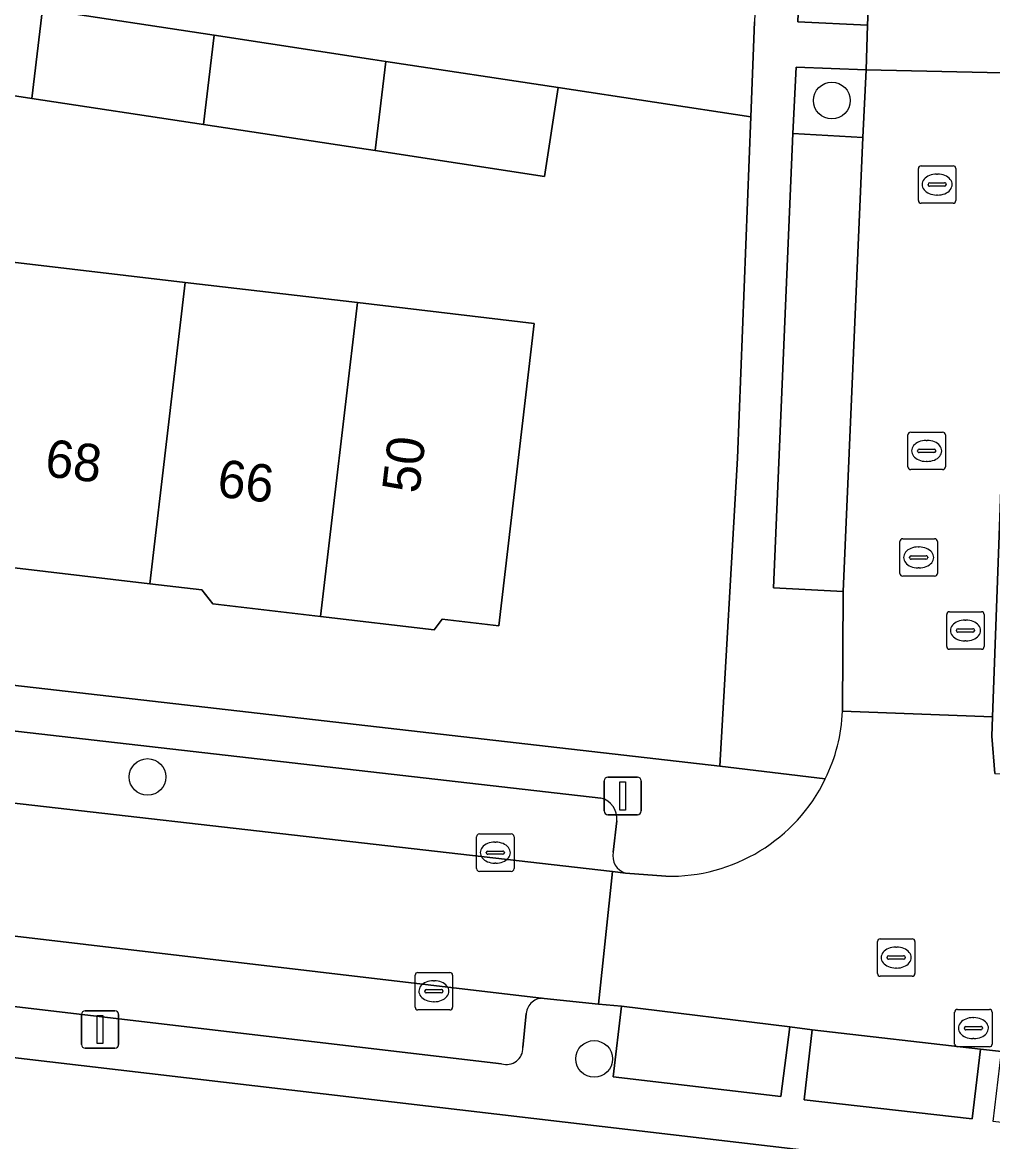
# Model space of a CAD drawing. Extents: x 162250 to 162661, y 380743 to 381606.
# Drawn here: x 162316.6 to 162342.5, y 380958.27 to 380988.14 of the extents above; entities that cross this region are included whole.
import ezdxf

# ---------------------------------------------------------------- set-up
doc = ezdxf.new("R2010")
doc.units = 0
for name, color, linetype in [('IMGEO_Boom', 7, 'Continuous'), ('IMGEO_Erf', 7, 'Continuous'), ('IMGEO_Groenvoorziening', 7, 'Continuous'), ('IMGEO_Kolk', 7, 'Continuous'), ('IMGEO_Lichtmast', 7, 'Continuous'), ('IMGEO_Pand', 7, 'Continuous'), ('IMGEO_Pand_nummerreeks', 7, 'Continuous'), ('IMGEO_Parkeervlak_open', 7, 'Continuous'), ('IMGEO_Rijbaan_lokaal_open', 7, 'Continuous'), ('IMGEO_Rioolput', 7, 'Continuous'), ('IMGEO_Voetpad_open', 7, 'Continuous')]:
    doc.layers.add(name, color=color, linetype=linetype)

msp = doc.modelspace()

# ---------------------------------------------------------------- linework, layer by layer
at = {"layer": 'IMGEO_Boom'}
for centre in [(162338.206, 380986.051), (162319.942, 380968.001), (162331.862, 380960.479)]:
    msp.add_circle(centre, 0.489, dxfattribs=at)
at = {"layer": 'IMGEO_Erf'}
msp.add_lwpolyline([(162321.44, 380985.411), (162316.858, 380986.109), (162312.278, 380986.806), (162307.698, 380987.503), (162303.115, 380988.2), (162298.535, 380988.897), (162294.161, 380989.563), (162293.955, 380989.594), (162289.217, 380990.315), (162289.578, 380992.684), (162285.702, 380993.275), (162283.759, 380976.44), (162283.492, 380974.216), (162335.219, 380968.294), (162335.689, 380976.508), (162336.042, 380985.614), (162330.898, 380986.396), (162330.538, 380984.027), (162326.021, 380984.714), (162325.595, 380984.779)], close=True, dxfattribs=at)
for points in [[(162297.948, 380983.904), (162302.547, 380983.363), (162307.147, 380982.822), (162311.746, 380982.282), (162316.345, 380981.741), (162320.945, 380981.2), (162325.544, 380980.66), (162330.262, 380980.105), (162329.314, 380972.033), (162327.806, 380972.21), (162327.594, 380971.925), (162324.559, 380972.282), (162321.687, 380972.62), (162321.391, 380972.995), (162319.999, 380973.159), (162315.4, 380973.699), (162310.801, 380974.24), (162306.201, 380974.781), (162301.602, 380975.321), (162297.003, 380975.862)], [(162396.364, 380951.153), (162282.368, 380964.496)]]:
    msp.add_lwpolyline(points, dxfattribs=at)
at = {"layer": 'IMGEO_Groenvoorziening'}
msp.add_lwpolyline([(162339.119, 380986.868), (162337.251, 380986.943), (162337.162, 380985.171), (162339.037, 380985.062)], close=True, dxfattribs=at)
at = {"layer": 'IMGEO_Kolk'}
for p, q in [((162340.515, 380983.383), (162340.515, 380984.235)), ((162340.59, 380984.309), (162341.442, 380984.309)), ((162341.516, 380984.235), (162341.516, 380983.383)), ((162341.003, 380984.089), (162341.028, 380984.089)), ((162340.774, 380983.803), (162340.774, 380983.815)), ((162341.212, 380983.766), (162340.814, 380983.766)), ((162340.817, 380983.852), (162341.215, 380983.852)), ((162341.258, 380983.815), (162341.258, 380983.803)), ((162341.026, 380983.529), (162341.001, 380983.529)), ((162341.442, 380983.309), (162340.59, 380983.309)), ((162340.236, 380976.276), (162340.236, 380977.128)), ((162340.311, 380977.202), (162341.163, 380977.202)), ((162341.237, 380977.128), (162341.237, 380976.276)), ((162340.724, 380976.982), (162340.749, 380976.982)), ((162340.495, 380976.696), (162340.495, 380976.708)), ((162340.933, 380976.659), (162340.535, 380976.659)), ((162340.538, 380976.745), (162340.936, 380976.745)), ((162340.979, 380976.708), (162340.979, 380976.696)), ((162341.163, 380976.202), (162340.311, 380976.202)), ((162340.747, 380976.422), (162340.722, 380976.422)), ((162328.723, 380965.556), (162328.723, 380966.408)), ((162328.798, 380966.482), (162329.65, 380966.482)), ((162329.724, 380966.408), (162329.724, 380965.556)), ((162329.025, 380966.025), (162329.423, 380966.025)), ((162329.211, 380966.262), (162329.236, 380966.262)), ((162328.982, 380965.976), (162328.982, 380965.988)), ((162329.42, 380965.939), (162329.022, 380965.939)), ((162329.466, 380965.988), (162329.466, 380965.976)), ((162329.65, 380965.482), (162328.798, 380965.482)), ((162329.234, 380965.702), (162329.209, 380965.702)), ((162327.159, 380962.785), (162328.011, 380962.785)), ((162327.084, 380961.859), (162327.084, 380962.711)), ((162327.572, 380962.565), (162327.597, 380962.565)), ((162328.085, 380962.711), (162328.085, 380961.859)), ((162327.343, 380962.279), (162327.343, 380962.291)), ((162327.781, 380962.242), (162327.383, 380962.242)), ((162327.386, 380962.328), (162327.784, 380962.328)), ((162327.827, 380962.291), (162327.827, 380962.279)), ((162327.595, 380962.005), (162327.57, 380962.005)), ((162328.011, 380961.785), (162327.159, 380961.785))]:
    msp.add_line(p, q, dxfattribs=at)
for points in [[(162340.515, 380983.383), (162340.515, 380984.235)], [(162340.59, 380984.309), (162341.442, 380984.309)], [(162341.516, 380984.235), (162341.516, 380983.383)], [(162341.442, 380983.309), (162340.59, 380983.309)], [(162340.236, 380976.276), (162340.236, 380977.128)], [(162340.311, 380977.202), (162341.163, 380977.202)], [(162341.237, 380977.128), (162341.237, 380976.276)], [(162341.163, 380976.202), (162340.311, 380976.202)], [(162328.723, 380965.556), (162328.723, 380966.408)], [(162328.798, 380966.482), (162329.65, 380966.482)], [(162329.724, 380966.408), (162329.724, 380965.556)], [(162329.65, 380965.482), (162328.798, 380965.482)], [(162327.159, 380962.785), (162328.011, 380962.785)], [(162327.084, 380961.859), (162327.084, 380962.711)], [(162328.085, 380962.711), (162328.085, 380961.859)], [(162328.011, 380961.785), (162327.159, 380961.785)]]:
    msp.add_lwpolyline(points, dxfattribs=at)
for centre, radius, start, end in [((162340.592, 380984.233), 0.0765, 91.552, 178.448), ((162340.592, 380984.233), 0.0765, 91.552, 178.448), ((162341.44, 380984.233), 0.0765, 1.552, 88.448), ((162341.44, 380984.233), 0.0765, 1.552, 88.448), ((162340.814, 380983.812), 0.0403, 85.8775, 175.7526), ((162340.811, 380983.802), 0.0366, 178.938, 274.7102), ((162341.215, 380983.809), 0.043, 264.8664, 352.4533), ((162341.219, 380983.814), 0.0386, 1.7309, 96.639), ((162340.592, 380983.385), 0.0765, 181.552, 268.448), ((162340.592, 380983.385), 0.0765, 181.552, 268.448), ((162341.44, 380983.385), 0.0765, 271.552, 358.448), ((162341.44, 380983.385), 0.0765, 271.552, 358.448), ((162340.313, 380977.126), 0.0765, 91.552, 178.448), ((162340.313, 380977.126), 0.0765, 91.552, 178.448), ((162341.161, 380977.126), 0.0765, 1.552, 88.448), ((162341.161, 380977.126), 0.0765, 1.552, 88.448), ((162340.535, 380976.705), 0.0403, 85.8775, 175.7526), ((162340.532, 380976.695), 0.0366, 178.938, 274.7102), ((162340.936, 380976.702), 0.043, 264.8664, 352.4533), ((162340.94, 380976.707), 0.0386, 1.7309, 96.639), ((162340.313, 380976.278), 0.0765, 181.552, 268.448), ((162340.313, 380976.278), 0.0765, 181.552, 268.448), ((162341.161, 380976.278), 0.0765, 271.552, 358.448), ((162341.161, 380976.278), 0.0765, 271.552, 358.448), ((162328.8, 380966.406), 0.0765, 91.552, 178.448), ((162328.8, 380966.406), 0.0765, 91.552, 178.448), ((162329.648, 380966.406), 0.0765, 1.552, 88.448), ((162329.648, 380966.406), 0.0765, 1.552, 88.448), ((162329.022, 380965.985), 0.0403, 85.8775, 175.7526), ((162329.427, 380965.987), 0.0386, 1.7309, 96.639), ((162329.019, 380965.975), 0.0366, 178.938, 274.7102), ((162329.423, 380965.982), 0.043, 264.8664, 352.4533), ((162328.8, 380965.558), 0.0765, 181.552, 268.448), ((162328.8, 380965.558), 0.0765, 181.552, 268.448), ((162329.648, 380965.558), 0.0765, 271.552, 358.448), ((162329.648, 380965.558), 0.0765, 271.552, 358.448), ((162327.161, 380962.709), 0.0765, 91.552, 178.448), ((162327.161, 380962.709), 0.0765, 91.552, 178.448), ((162328.009, 380962.709), 0.0765, 1.552, 88.448), ((162328.009, 380962.709), 0.0765, 1.552, 88.448), ((162327.383, 380962.288), 0.0403, 85.8775, 175.7526), ((162327.38, 380962.278), 0.0366, 178.938, 274.7102), ((162327.784, 380962.285), 0.043, 264.8664, 352.4533), ((162327.788, 380962.29), 0.0386, 1.7309, 96.639), ((162327.161, 380961.861), 0.0765, 181.552, 268.448), ((162327.161, 380961.861), 0.0765, 181.552, 268.448), ((162328.009, 380961.861), 0.0765, 271.552, 358.448), ((162328.009, 380961.861), 0.0765, 271.552, 358.448)]:
    msp.add_arc(centre, radius, start, end, dxfattribs=at)
for centre, major_axis, ratio, start_param, end_param in [((162341.002, 380983.809), (-0.387, 0.002), 0.722429, 4.712389, 7.853982), ((162341.027, 380983.809), (-0.39, 0.002), 0.717154, 1.570796, 4.712389), ((162340.723, 380976.702), (-0.387, 0.002), 0.722429, 4.712389, 7.853982), ((162340.748, 380976.702), (-0.39, 0.002), 0.717154, 1.570796, 4.712389), ((162329.21, 380965.982), (-0.387, 0.002), 0.722429, 4.712389, 7.853982), ((162329.235, 380965.982), (-0.39, 0.002), 0.717154, 1.570796, 4.712389), ((162327.571, 380962.285), (-0.387, 0.002), 0.722429, 4.712389, 7.853982), ((162327.596, 380962.285), (-0.39, 0.002), 0.717154, 1.570796, 4.712389)]:
    msp.add_ellipse(centre, major_axis=major_axis, ratio=ratio, start_param=start_param, end_param=end_param, dxfattribs=at)
at = {"layer": 'IMGEO_Lichtmast'}
for p, q in [((162332.128, 380967.095), (162332.128, 380967.895)), ((162332.128, 380967.895), (162332.128, 380967.095)), ((162332.228, 380967.995), (162333.018, 380967.995)), ((162333.018, 380967.995), (162332.228, 380967.995)), ((162333.118, 380967.895), (162333.118, 380967.095)), ((162333.118, 380967.095), (162333.118, 380967.895)), ((162333.018, 380966.995), (162332.228, 380966.995)), ((162332.228, 380966.995), (162333.018, 380966.995)), ((162318.181, 380960.864), (162318.181, 380961.664)), ((162318.181, 380961.664), (162318.181, 380960.864)), ((162318.281, 380961.764), (162319.071, 380961.764)), ((162319.071, 380961.764), (162318.281, 380961.764)), ((162319.171, 380961.664), (162319.171, 380960.864)), ((162319.171, 380960.864), (162319.171, 380961.664)), ((162319.071, 380960.764), (162318.281, 380960.764)), ((162318.281, 380960.764), (162319.071, 380960.764))]:
    msp.add_line(p, q, dxfattribs=at)
for points in [[(162332.548, 380967.87), (162332.698, 380967.87), (162332.698, 380967.12), (162332.548, 380967.12), (162332.548, 380967.87)], [(162318.601, 380961.639), (162318.751, 380961.639), (162318.751, 380960.889), (162318.601, 380960.889), (162318.601, 380961.639)]]:
    msp.add_lwpolyline(points, dxfattribs=at)
for centre, start, end in [((162332.228, 380967.895), 90, 180), ((162332.228, 380967.895), 90, 180), ((162333.018, 380967.895), 0, 90), ((162333.018, 380967.895), 360, 90), ((162332.228, 380967.095), 180, 270), ((162332.228, 380967.095), 180, 270), ((162333.018, 380967.095), 270, 0), ((162333.018, 380967.095), 270, 0), ((162318.281, 380961.664), 90, 180), ((162318.281, 380961.664), 90, 180), ((162319.071, 380961.664), 0, 90), ((162319.071, 380961.664), 360, 90), ((162318.281, 380960.864), 180, 270), ((162318.281, 380960.864), 180, 270), ((162319.071, 380960.864), 270, 0), ((162319.071, 380960.864), 270, 0)]:
    msp.add_arc(centre, 0.1, start, end, dxfattribs=at)
at = {"layer": 'IMGEO_Pand'}
for points in [[(162312.278, 380986.806), (162316.858, 380986.109), (162317.138, 380988.49), (162312.557, 380989.187)], [(162321.721, 380987.792), (162317.138, 380988.49), (162316.858, 380986.109), (162321.44, 380985.411)], [(162321.721, 380987.792), (162321.44, 380985.411), (162325.595, 380984.779), (162326.021, 380984.714), (162326.301, 380987.095), (162325.955, 380987.148)], [(162326.021, 380984.714), (162330.538, 380984.027), (162330.898, 380986.396), (162326.301, 380987.095)], [(162316.345, 380981.741), (162315.4, 380973.699), (162319.999, 380973.159), (162320.945, 380981.2)], [(162325.544, 380980.66), (162320.945, 380981.2), (162319.999, 380973.159), (162321.391, 380972.995), (162321.687, 380972.62), (162324.559, 380972.282)], [(162325.544, 380980.66), (162324.559, 380972.282), (162327.594, 380971.925), (162327.806, 380972.21), (162329.314, 380972.033), (162330.262, 380980.105)]]:
    msp.add_lwpolyline(points, close=True, dxfattribs=at)
at = {"layer": 'IMGEO_Parkeervlak_open'}
for points in [[(162340.038, 381010.111), (162338.156, 381010.198), (162337.294, 380988.148), (162339.157, 380988.064), (162339.37, 380992.927)], [(162344.989, 380985.516), (162343.084, 380985.588), (162342.495, 380969.61), (162342.476, 380969.092), (162342.553, 380968.091), (162344.349, 380968.083)], [(162339.037, 380985.062), (162337.162, 380985.171), (162336.646, 380973.052), (162338.509, 380972.948)], [(162337.083, 380961.332), (162332.589, 380961.89), (162332.373, 380959.999), (162336.845, 380959.473)], [(162337.683, 380961.253), (162337.463, 380959.389), (162341.953, 380958.882), (162342.172, 380960.742)]]:
    msp.add_lwpolyline(points, close=True, dxfattribs=at)
for points in [[(162332.037, 380967.44), (162286.174, 380972.683)], [(162284.995, 380970.888), (162332.355, 380965.483), (162332.699, 380965.436)], [(162330.529, 380962.093), (162284.836, 380967.471)], [(162332.37, 380965.994), (162332.469, 380966.833)], [(162285.595, 380965.499), (162329.39, 380960.351)], [(162329.959, 380960.782), (162330.052, 380961.693)]]:
    msp.add_lwpolyline(points, dxfattribs=at)
for centre, radius, start, end in [((162331.902, 380966.887), 0.569, 354.5842, 76.2945), ((162332.839, 380965.894), 0.479, 168.0185, 253.0292), ((162330.482, 380961.665), 0.431, 83.6791, 176.2856), ((162329.526, 380960.762), 0.433, 251.6612, 2.6244)]:
    msp.add_arc(centre, radius, start, end, dxfattribs=at)
at = {"layer": 'IMGEO_Rijbaan_lokaal_open'}
for points in [[(162339.157, 380988.064), (162339.119, 380986.868), (162343.163, 380986.78), (162343.397, 380992.747), (162339.37, 380992.927)], [(162343.084, 380985.588), (162343.163, 380986.78), (162339.119, 380986.868), (162339.037, 380985.062), (162338.509, 380972.948), (162338.492, 380969.758), (162342.495, 380969.61)], [(162284.995, 380970.888), (162284.107, 380971.014), (162283.032, 380971.129), (162282.665, 380967.703), (162283.759, 380967.586), (162284.836, 380967.471), (162330.529, 380962.093), (162331.977, 380961.942), (162332.355, 380965.483)]]:
    msp.add_lwpolyline(points, close=True, dxfattribs=at)
for points in [[(162342.553, 380968.091), (162342.476, 380969.092), (162342.495, 380969.61), (162338.492, 380969.758)], [(162333.779, 380965.354), (162332.699, 380965.436), (162332.355, 380965.483), (162331.977, 380961.942), (162332.589, 380961.89), (162337.083, 380961.332), (162337.683, 380961.253), (162342.172, 380960.742), (162342.735, 380960.674), (162346.981, 380960.157), (162347.688, 380960.071), (162348.113, 380963.62), (162347.022, 380963.772)]]:
    msp.add_lwpolyline(points, dxfattribs=at)
for centre, radius, start, end in [((162333.909, 380969.959), 4.587, 333.9951, 357.486), ((162333.887, 380969.961), 4.608, 268.663, 334.0969)]:
    msp.add_arc(centre, radius, start, end, dxfattribs=at)
at = {"layer": 'IMGEO_Rioolput'}
for p, q in [((162340.022, 380973.433), (162340.022, 380974.285)), ((162340.097, 380974.359), (162340.949, 380974.359)), ((162340.51, 380974.139), (162340.535, 380974.139)), ((162341.023, 380974.285), (162341.023, 380973.433)), ((162340.281, 380973.853), (162340.281, 380973.865)), ((162340.719, 380973.816), (162340.321, 380973.816)), ((162340.324, 380973.902), (162340.722, 380973.902)), ((162340.765, 380973.865), (162340.765, 380973.853)), ((162340.533, 380973.579), (162340.508, 380973.579)), ((162340.949, 380973.359), (162340.097, 380973.359)), ((162341.272, 380971.484), (162341.272, 380972.336)), ((162341.347, 380972.41), (162342.199, 380972.41)), ((162342.273, 380972.336), (162342.273, 380971.484)), ((162341.76, 380972.19), (162341.785, 380972.19)), ((162341.531, 380971.904), (162341.531, 380971.916)), ((162341.969, 380971.867), (162341.571, 380971.867)), ((162341.574, 380971.953), (162341.972, 380971.953)), ((162342.015, 380971.916), (162342.015, 380971.904)), ((162342.199, 380971.41), (162341.347, 380971.41)), ((162341.783, 380971.63), (162341.758, 380971.63)), ((162339.498, 380963.683), (162340.35, 380963.683)), ((162339.423, 380962.757), (162339.423, 380963.609)), ((162339.911, 380963.463), (162339.936, 380963.463)), ((162340.424, 380963.609), (162340.424, 380962.757)), ((162339.682, 380963.177), (162339.682, 380963.189)), ((162340.12, 380963.14), (162339.722, 380963.14)), ((162339.725, 380963.226), (162340.123, 380963.226)), ((162340.166, 380963.189), (162340.166, 380963.177)), ((162339.934, 380962.903), (162339.909, 380962.903)), ((162340.35, 380962.683), (162339.498, 380962.683)), ((162341.484, 380960.874), (162341.484, 380961.726)), ((162341.559, 380961.8), (162342.411, 380961.8)), ((162341.972, 380961.58), (162341.997, 380961.58)), ((162342.485, 380961.726), (162342.485, 380960.874)), ((162341.743, 380961.294), (162341.743, 380961.306)), ((162342.181, 380961.257), (162341.783, 380961.257)), ((162341.786, 380961.343), (162342.184, 380961.343)), ((162342.227, 380961.306), (162342.227, 380961.294)), ((162341.995, 380961.02), (162341.97, 380961.02)), ((162342.411, 380960.8), (162341.559, 380960.8))]:
    msp.add_line(p, q, dxfattribs=at)
for points in [[(162340.022, 380973.433), (162340.022, 380974.285)], [(162340.097, 380974.359), (162340.949, 380974.359)], [(162341.023, 380974.285), (162341.023, 380973.433)], [(162340.949, 380973.359), (162340.097, 380973.359)], [(162341.272, 380971.484), (162341.272, 380972.336)], [(162341.347, 380972.41), (162342.199, 380972.41)], [(162342.273, 380972.336), (162342.273, 380971.484)], [(162342.199, 380971.41), (162341.347, 380971.41)], [(162339.498, 380963.683), (162340.35, 380963.683)], [(162339.423, 380962.757), (162339.423, 380963.609)], [(162340.424, 380963.609), (162340.424, 380962.757)], [(162340.35, 380962.683), (162339.498, 380962.683)], [(162341.484, 380960.874), (162341.484, 380961.726)], [(162341.559, 380961.8), (162342.411, 380961.8)], [(162342.485, 380961.726), (162342.485, 380960.874)], [(162342.411, 380960.8), (162341.559, 380960.8)]]:
    msp.add_lwpolyline(points, dxfattribs=at)
for centre, radius, start, end in [((162340.099, 380974.283), 0.0765, 91.552, 178.448), ((162340.099, 380974.283), 0.0765, 91.552, 178.448), ((162340.947, 380974.283), 0.0765, 1.552, 88.448), ((162340.947, 380974.283), 0.0765, 1.552, 88.448), ((162340.321, 380973.862), 0.0403, 85.8775, 175.7526), ((162340.318, 380973.852), 0.0366, 178.938, 274.7102), ((162340.722, 380973.859), 0.043, 264.8664, 352.4533), ((162340.726, 380973.864), 0.0386, 1.7309, 96.639), ((162340.099, 380973.435), 0.0765, 181.552, 268.448), ((162340.099, 380973.435), 0.0765, 181.552, 268.448), ((162340.947, 380973.435), 0.0765, 271.552, 358.448), ((162340.947, 380973.435), 0.0765, 271.552, 358.448), ((162341.349, 380972.334), 0.0765, 91.552, 178.448), ((162341.349, 380972.334), 0.0765, 91.552, 178.448), ((162342.197, 380972.334), 0.0765, 1.552, 88.448), ((162342.197, 380972.334), 0.0765, 1.552, 88.448), ((162341.571, 380971.913), 0.0403, 85.8775, 175.7526), ((162341.568, 380971.903), 0.0366, 178.938, 274.7102), ((162341.972, 380971.91), 0.043, 264.8664, 352.4533), ((162341.976, 380971.915), 0.0386, 1.7309, 96.639), ((162341.349, 380971.486), 0.0765, 181.552, 268.448), ((162341.349, 380971.486), 0.0765, 181.552, 268.448), ((162342.197, 380971.486), 0.0765, 271.552, 358.448), ((162342.197, 380971.486), 0.0765, 271.552, 358.448), ((162339.5, 380963.607), 0.0765, 91.552, 178.448), ((162339.5, 380963.607), 0.0765, 91.552, 178.448), ((162340.348, 380963.607), 0.0765, 1.552, 88.448), ((162340.348, 380963.607), 0.0765, 1.552, 88.448), ((162339.722, 380963.186), 0.0403, 85.8775, 175.7526), ((162339.719, 380963.176), 0.0366, 178.938, 274.7102), ((162340.123, 380963.183), 0.043, 264.8664, 352.4533), ((162340.127, 380963.188), 0.0386, 1.7309, 96.639), ((162339.5, 380962.759), 0.0765, 181.552, 268.448), ((162339.5, 380962.759), 0.0765, 181.552, 268.448), ((162340.348, 380962.759), 0.0765, 271.552, 358.448), ((162340.348, 380962.759), 0.0765, 271.552, 358.448), ((162341.561, 380961.724), 0.0765, 91.552, 178.448), ((162341.561, 380961.724), 0.0765, 91.552, 178.448), ((162342.409, 380961.724), 0.0765, 1.552, 88.448), ((162342.409, 380961.724), 0.0765, 1.552, 88.448), ((162341.783, 380961.303), 0.0403, 85.8775, 175.7526), ((162341.78, 380961.293), 0.0366, 178.938, 274.7102), ((162342.184, 380961.3), 0.043, 264.8664, 352.4533), ((162342.188, 380961.305), 0.0386, 1.7309, 96.639), ((162341.561, 380960.876), 0.0765, 181.552, 268.448), ((162341.561, 380960.876), 0.0765, 181.552, 268.448), ((162342.409, 380960.876), 0.0765, 271.552, 358.448), ((162342.409, 380960.876), 0.0765, 271.552, 358.448)]:
    msp.add_arc(centre, radius, start, end, dxfattribs=at)
for centre, major_axis, ratio, start_param, end_param in [((162340.509, 380973.859), (-0.387, 0.002), 0.722429, 4.712389, 7.853982), ((162340.534, 380973.859), (-0.39, 0.002), 0.717154, 1.570796, 4.712389), ((162341.759, 380971.91), (-0.387, 0.002), 0.722429, 4.712389, 7.853982), ((162341.784, 380971.91), (-0.39, 0.002), 0.717154, 1.570796, 4.712389), ((162339.91, 380963.183), (-0.387, 0.002), 0.722429, 4.712389, 7.853982), ((162339.935, 380963.183), (-0.39, 0.002), 0.717154, 1.570796, 4.712389), ((162341.971, 380961.3), (-0.387, 0.002), 0.722429, 4.712389, 7.853982), ((162341.996, 380961.3), (-0.39, 0.002), 0.717154, 1.570796, 4.712389)]:
    msp.add_ellipse(centre, major_axis=major_axis, ratio=ratio, start_param=start_param, end_param=end_param, dxfattribs=at)
at = {"layer": 'IMGEO_Voetpad_open'}
for points in [[(162341.565, 381113.994), (162340.767, 381095.921), (162340.701, 381094.418), (162338.044, 381034.203), (162336.016, 381034.263), (162335.584, 381024.354), (162337.62, 381024.184), (162336.6, 381000), (162336.141, 380988.151), (162336.042, 380985.614), (162335.689, 380976.508), (162335.219, 380968.294), (162338.032, 380967.948)], [(162338.492, 380969.758), (162338.509, 380972.948), (162336.646, 380973.052), (162337.162, 380985.171), (162337.251, 380986.943), (162339.119, 380986.868), (162339.157, 380988.064), (162337.294, 380988.148), (162338.156, 381010.198)], [(162317.138, 380988.49), (162321.721, 380987.792), (162325.955, 380987.148), (162326.301, 380987.095), (162330.898, 380986.396), (162336.042, 380985.614), (162336.141, 380988.151)], [(162338.032, 380967.948), (162335.219, 380968.294), (162283.492, 380974.216)], [(162286.174, 380972.683), (162332.037, 380967.44)], [(162284.836, 380967.471), (162283.759, 380967.586), (162282.665, 380967.703), (162282.368, 380964.496), (162396.364, 380951.153)], [(162332.469, 380966.833), (162332.37, 380965.994)], [(162329.39, 380960.351), (162285.595, 380965.499)], [(162332.699, 380965.436), (162333.779, 380965.354)], [(162348.578, 380959.963), (162347.688, 380960.071), (162346.981, 380960.157), (162346.756, 380958.297), (162342.509, 380958.81), (162342.735, 380960.674), (162342.172, 380960.742), (162341.953, 380958.882), (162337.463, 380959.389), (162337.683, 380961.253), (162337.083, 380961.332), (162336.845, 380959.473), (162332.373, 380959.999), (162332.589, 380961.89), (162331.977, 380961.942), (162330.529, 380962.093)], [(162330.052, 380961.693), (162329.959, 380960.782)]]:
    msp.add_lwpolyline(points, dxfattribs=at)
for centre, radius, start, end in [((162333.909, 380969.959), 4.587, 333.9951, 357.486), ((162333.887, 380969.961), 4.608, 268.663, 334.0969), ((162331.902, 380966.887), 0.569, 354.5842, 76.2945), ((162332.839, 380965.894), 0.479, 168.0185, 253.0292), ((162330.482, 380961.665), 0.431, 83.6791, 176.2856), ((162329.526, 380960.762), 0.433, 251.6612, 2.6244)]:
    msp.add_arc(centre, radius, start, end, dxfattribs=at)

# ---------------------------------------------------------------- texts
at = {"layer": 'IMGEO_Pand_nummerreeks'}
for s, rotation, p in [('50', 83.3017, (162327.19, 380975.545)), ('68', 353.2953, (162317.176, 380976.027)), ('66', 353.2953, (162321.772, 380975.487))]:
    msp.add_text(s, height=1, rotation=rotation, dxfattribs=at).set_placement(p)

doc.saveas('drawing.dxf')
